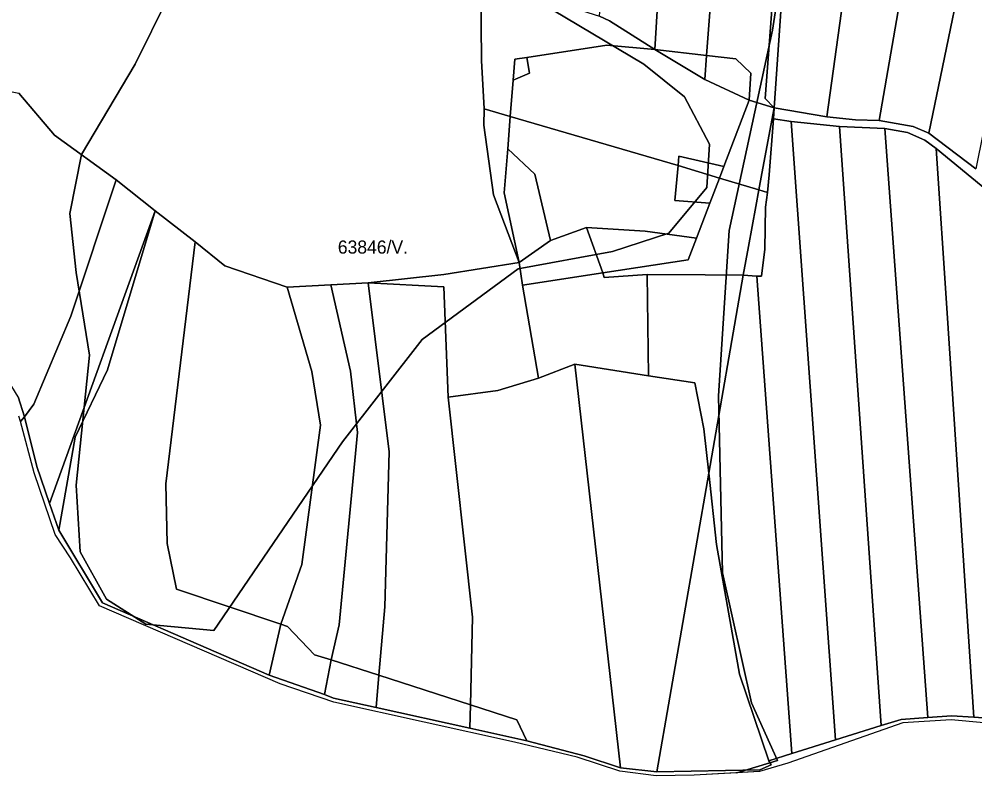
# Model space of a CAD drawing. Extents: x -521261 to -517465, y -1182764 to -1179456.
# Drawn here: x -519763.3 to -519398.8, y -1182348.9 to -1182060.3 of the extents above; entities that cross this region are included whole.
import ezdxf

# ---------------------------------------------------------------- set-up
doc = ezdxf.new("R2010")
doc.units = 0
for name, color, linetype in [('95560013', 7, 'Continuous'), ('95640013', 7, 'Continuous'), ('95660013', 7, 'Continuous')]:
    doc.layers.add(name, color=color, linetype=linetype)

msp = doc.modelspace()

# ---------------------------------------------------------------- linework, layer by layer
at = {"layer": '95560013'}
for points in [[(-519516.92, -1181853.55), (-519508.53, -1181867.8), (-519520.78, -1182071.93), (-519538.16, -1182060.97), (-519541.91, -1182059.26), (-519523.41, -1181832.63)], [(-519487.9, -1181902.3), (-519501.15, -1182074.26), (-519520.78, -1182071.93), (-519508.53, -1181867.8)], [(-519467.21, -1181936.45), (-519478.73, -1182090.66), (-519475.35, -1182094.14), (-519484.89, -1182091.25), (-519484.16, -1182080.96), (-519489.93, -1182075.44), (-519501.15, -1182074.26), (-519487.9, -1181902.3)], [(-519379, -1181923.14), (-519358.09, -1181917.7), (-519398.37, -1182117.43), (-519416.36, -1182103.79)], [(-519406.08, -1181930.21), (-519379, -1181923.14), (-519416.36, -1182103.79), (-519422.3, -1182101.28), (-519435.27, -1182098.99)], [(-519432.56, -1181934.33), (-519406.08, -1181930.21), (-519435.27, -1182098.99), (-519444.29, -1182098.72), (-519455.23, -1182097.62)], [(-519464.46, -1181937.6), (-519432.56, -1181934.33), (-519455.23, -1182097.62), (-519475.35, -1182094.14)], [(-519587.21, -1182048.68), (-519567.33, -1182051.07), (-519541.91, -1182059.26), (-519538.16, -1182060.97), (-519520.78, -1182071.93), (-519539.14, -1182070.29), (-519569.64, -1182074.9), (-519574.23, -1182075.58), (-519574.86, -1182083.63), (-519575.95, -1182097.41), (-519585.88, -1182094.5), (-519586.88, -1182076.07)], [(-519763.35, -1182088.59), (-519749.77, -1182104.53), (-519726.21, -1182121.6), (-519743.53, -1182173.62), (-519757.71, -1182207.2), (-519761.2, -1182211.94), (-519763.67, -1182204.39), (-519774.58, -1182186.72), (-519789.17, -1182168.41), (-519776.4, -1182108.82), (-519776, -1182086.02)], [(-519475.35, -1182094.14), (-519480.05, -1182119.2), (-519481.13, -1182125.46), (-519496.19, -1182120.92), (-519494.5, -1182116.48), (-519484.89, -1182091.25)], [(-519585.88, -1182094.5), (-519575.95, -1182097.41), (-519576.94, -1182109.82), (-519578.27, -1182126.51), (-519572.56, -1182153.16), (-519582.31, -1182127.3), (-519586.07, -1182100.76)], [(-519475.58, -1182098.3), (-519477.24, -1182119.69), (-519477.83, -1182126.45), (-519481.13, -1182125.46), (-519480.05, -1182119.2), (-519475.35, -1182094.14)], [(-519468.81, -1182099.37), (-519451.94, -1182335.19), (-519468.6, -1182340.44), (-519481.96, -1182158.34), (-519480.13, -1182158.37), (-519478.87, -1182148.03), (-519478.68, -1182132.07), (-519477.83, -1182126.45), (-519477.24, -1182119.69), (-519475.58, -1182098.3)], [(-519450.44, -1182101.26), (-519434.44, -1182329.73), (-519451.94, -1182335.19), (-519468.81, -1182099.37)], [(-519433.08, -1182101.99), (-519416.65, -1182326.64), (-519426.88, -1182327.36), (-519434.44, -1182329.73), (-519450.44, -1182101.26)], [(-519424.5, -1182103.59), (-519417.83, -1182106.43), (-519413.54, -1182109.63), (-519409.28, -1182172.45), (-519399.15, -1182326.59), (-519407.66, -1182325.98), (-519416.65, -1182326.64), (-519433.08, -1182101.99)], [(-519394.19, -1182125.51), (-519378.51, -1182327.95), (-519378.06, -1182331.92), (-519379.66, -1182331.75), (-519384.54, -1182331.48), (-519384.34, -1182329.69), (-519384.76, -1182327.55), (-519399.15, -1182326.59), (-519409.28, -1182172.45), (-519413.54, -1182109.63)], [(-519711.36, -1182133.5), (-519751.72, -1182245.06), (-519756.54, -1182230.97), (-519761.2, -1182211.94), (-519757.71, -1182207.2), (-519743.53, -1182173.62), (-519726.21, -1182121.6)], [(-519496.19, -1182120.92), (-519481.13, -1182125.46), (-519482.3, -1182131.8), (-519485.13, -1182147.09), (-519487.14, -1182158), (-519501.6, -1182157.81), (-519523.78, -1182157.71), (-519540.1, -1182158.81), (-519540.71, -1182157.1), (-519508.06, -1182152.07), (-519504.91, -1182143.82), (-519499.84, -1182130.5)], [(-519481.13, -1182125.46), (-519477.83, -1182126.45), (-519478.68, -1182132.07), (-519478.87, -1182148.03), (-519480.13, -1182158.37), (-519481.96, -1182158.34), (-519487.14, -1182158), (-519485.13, -1182147.09), (-519482.3, -1182131.8)], [(-519696.09, -1182145.3), (-519684.77, -1182154.35), (-519661.04, -1182162.55), (-519651.69, -1182194.65), (-519648.28, -1182215.2), (-519655.4, -1182268.32), (-519663.51, -1182291.01), (-519703.24, -1182277.77), (-519706.82, -1182260.27), (-519707.29, -1182237.56)], [(-519572.56, -1182153.16), (-519571.25, -1182161.79), (-519565.14, -1182197.26), (-519580.66, -1182201.92), (-519599.71, -1182204.55), (-519601.3, -1182162.43), (-519630.15, -1182160.89), (-519601.35, -1182157.71)], [(-519540.1, -1182158.81), (-519523.78, -1182157.71), (-519523.29, -1182196.42), (-519551.35, -1182191.91), (-519565.14, -1182197.26), (-519571.25, -1182161.79), (-519540.71, -1182157.1)], [(-519523.78, -1182157.71), (-519501.6, -1182157.81), (-519487.14, -1182158), (-519500.27, -1182233.5), (-519502.08, -1182216.63), (-519505.57, -1182199.06), (-519523.29, -1182196.42)], [(-519481.96, -1182158.34), (-519468.6, -1182340.44), (-519477.29, -1182343.21), (-519488.55, -1182310.14), (-519497.35, -1182260.74), (-519500.27, -1182233.5), (-519487.14, -1182158)], [(-519644.35, -1182161.65), (-519636.84, -1182194.61), (-519634.17, -1182218), (-519641.18, -1182291.32), (-519644.33, -1182304.67), (-519650.66, -1182302.72), (-519660.94, -1182291.93), (-519663.51, -1182291.01), (-519655.4, -1182268.32), (-519648.28, -1182215.2), (-519651.69, -1182194.65), (-519661.04, -1182162.55)], [(-519630.15, -1182160.89), (-519622.19, -1182225.4), (-519623.76, -1182284.43), (-519626.06, -1182310.56), (-519644.33, -1182304.67), (-519641.18, -1182291.32), (-519634.17, -1182218), (-519636.84, -1182194.61), (-519644.35, -1182161.65)], [(-519630.15, -1182160.89), (-519601.3, -1182162.43), (-519599.71, -1182204.55), (-519590.36, -1182288.36), (-519591.16, -1182321.81), (-519626.06, -1182310.56), (-519623.76, -1182284.43), (-519622.19, -1182225.4)], [(-519551.35, -1182191.91), (-519533.95, -1182345.85), (-519547.75, -1182341.3), (-519569.7, -1182335.58), (-519573.45, -1182327.52), (-519591.16, -1182321.81), (-519590.36, -1182288.36), (-519599.71, -1182204.55), (-519580.66, -1182201.92), (-519565.14, -1182197.26)], [(-519523.29, -1182196.42), (-519505.57, -1182199.06), (-519502.08, -1182216.63), (-519500.27, -1182233.5), (-519520.08, -1182347.41), (-519533.95, -1182345.85), (-519551.35, -1182191.91)], [(-519500.27, -1182233.5), (-519497.35, -1182260.74), (-519488.55, -1182310.14), (-519477.29, -1182343.21), (-519476.43, -1182344.74), (-519480.75, -1182346.56), (-519520.08, -1182347.41)]]:
    msp.add_lwpolyline(points, close=True, dxfattribs=at)
for points in [[(-519587.21, -1182048.68), (-519586.88, -1182076.07), (-519585.88, -1182094.5), (-519586.07, -1182100.76), (-519582.31, -1182127.3), (-519572.56, -1182153.16), (-519601.35, -1182157.71), (-519630.15, -1182160.89), (-519644.35, -1182161.65), (-519661.04, -1182162.55), (-519684.77, -1182154.35), (-519696.09, -1182145.3), (-519711.36, -1182133.5), (-519726.21, -1182121.6), (-519749.77, -1182104.53), (-519763.35, -1182088.59)], [(-519394.19, -1182125.51), (-519413.54, -1182109.63), (-519417.83, -1182106.43), (-519424.5, -1182103.59), (-519433.08, -1182101.99), (-519450.44, -1182101.26), (-519468.81, -1182099.37), (-519475.58, -1182098.3), (-519475.35, -1182094.14), (-519455.23, -1182097.62), (-519444.29, -1182098.72), (-519435.27, -1182098.99), (-519422.3, -1182101.28), (-519416.36, -1182103.79), (-519398.37, -1182117.43)], [(-519763.67, -1182204.39), (-519761.2, -1182211.94), (-519762.82, -1182213.81), (-519763.37, -1182211.75)]]:
    msp.add_lwpolyline(points, dxfattribs=at)
at = {"layer": '95640013'}
for points in [[(-519531.67, -1181805.67), (-519527.59, -1181810.9), (-519514.79, -1181851.2), (-519465.56, -1181934.8), (-519464.46, -1181937.6), (-519475.35, -1182094.14), (-519478.73, -1182090.66), (-519467.21, -1181936.45), (-519487.9, -1181902.3), (-519508.53, -1181867.8), (-519516.92, -1181853.55), (-519523.41, -1181832.63), (-519529.03, -1181814.46), (-519530.74, -1181812.82)], [(-519539.14, -1182070.29), (-519520.78, -1182071.93), (-519501.8, -1182083.31), (-519484.89, -1182091.25), (-519494.5, -1182116.48), (-519511.65, -1182112.55), (-519511.94, -1182116.17), (-519575.95, -1182097.41), (-519574.86, -1182083.63), (-519568.69, -1182080.98), (-519569.64, -1182074.9)], [(-519520.78, -1182071.93), (-519501.15, -1182074.26), (-519501.8, -1182083.31)], [(-519501.15, -1182074.26), (-519489.93, -1182075.44), (-519484.16, -1182080.96), (-519484.89, -1182091.25), (-519501.8, -1182083.31)], [(-519574.23, -1182075.58), (-519569.64, -1182074.9), (-519568.69, -1182080.98), (-519574.86, -1182083.63)], [(-519576.94, -1182109.82), (-519575.95, -1182097.41), (-519511.94, -1182116.17), (-519513.2, -1182129.51), (-519499.84, -1182130.5), (-519504.91, -1182143.82), (-519524.51, -1182141.21), (-519546.92, -1182139.79), (-519560.67, -1182144.76), (-519566.54, -1182119.49)], [(-519576.94, -1182109.82), (-519566.54, -1182119.49), (-519560.67, -1182144.76), (-519572.56, -1182153.16), (-519578.27, -1182126.51)], [(-519511.94, -1182116.17), (-519511.65, -1182112.55), (-519494.5, -1182116.48), (-519496.19, -1182120.92)], [(-519511.94, -1182116.17), (-519496.19, -1182120.92), (-519499.84, -1182130.5), (-519513.2, -1182129.51)], [(-519711.36, -1182133.5), (-519729.53, -1182194.03), (-519741.92, -1182219.81), (-519748.2, -1182255.2), (-519751.72, -1182245.06)], [(-519696.09, -1182145.3), (-519707.29, -1182237.56), (-519706.82, -1182260.27), (-519703.24, -1182277.77), (-519663.51, -1182291.01), (-519667.93, -1182310.48), (-519731.54, -1182282.88), (-519748.2, -1182255.2), (-519741.92, -1182219.81), (-519729.53, -1182194.03), (-519711.36, -1182133.5)], [(-519546.92, -1182139.79), (-519540.71, -1182157.1), (-519571.25, -1182161.79), (-519572.56, -1182153.16), (-519560.67, -1182144.76)], [(-519524.51, -1182141.21), (-519504.91, -1182143.82), (-519508.06, -1182152.07), (-519540.71, -1182157.1), (-519546.92, -1182139.79)], [(-519660.94, -1182291.93), (-519650.66, -1182302.72), (-519644.33, -1182304.67), (-519646.86, -1182317.92), (-519667.93, -1182310.48), (-519663.51, -1182291.01)], [(-519626.06, -1182310.56), (-519627.14, -1182322.79), (-519643.33, -1182319.25), (-519646.86, -1182317.92), (-519644.33, -1182304.67)], [(-519591.16, -1182321.81), (-519591.37, -1182330.69), (-519627.14, -1182322.79), (-519626.06, -1182310.56)], [(-519573.45, -1182327.52), (-519569.7, -1182335.58), (-519591.37, -1182330.69), (-519591.16, -1182321.81)]]:
    msp.add_lwpolyline(points, close=True, dxfattribs=at)
msp.add_lwpolyline([(-519384.34, -1182329.69), (-519407.79, -1182327.6), (-519426.27, -1182328.75), (-519470.15, -1182344.05), (-519480.86, -1182347.27), (-519505.85, -1182348.7), (-519520.37, -1182348.92), (-519534.18, -1182347.06), (-519550.42, -1182341.81), (-519574.39, -1182336.12), (-519643.28, -1182320.8), (-519663.67, -1182313.8), (-519732.68, -1182284.01), (-519743.73, -1182265.8), (-519749.55, -1182256.9), (-519757.57, -1182233.31), (-519762.82, -1182213.81), (-519761.2, -1182211.94), (-519756.54, -1182230.97), (-519751.72, -1182245.06), (-519748.2, -1182255.2), (-519731.54, -1182282.88), (-519667.93, -1182310.48), (-519646.86, -1182317.92), (-519643.33, -1182319.25), (-519627.14, -1182322.79), (-519591.37, -1182330.69), (-519569.7, -1182335.58), (-519547.75, -1182341.3), (-519533.95, -1182345.85), (-519520.08, -1182347.41), (-519480.75, -1182346.56), (-519476.43, -1182344.74), (-519477.29, -1182343.21), (-519468.6, -1182340.44), (-519451.94, -1182335.19), (-519434.44, -1182329.73), (-519426.88, -1182327.36), (-519416.65, -1182326.64), (-519407.66, -1182325.98), (-519399.15, -1182326.59), (-519384.76, -1182327.55)], dxfattribs=at)
at = {"layer": '95660013'}
for points in [[(-519466, -1182000), (-519476, -1182064.5), (-519492.5, -1182141), (-519496.5, -1182204), (-519495, -1182271.5), (-519484, -1182321), (-519474, -1182343), (-519489.54, -1182347.77), (-519505.85, -1182348.7), (-519520.37, -1182348.92), (-519534.18, -1182347.06), (-519550.42, -1182341.81), (-519574.39, -1182336.12), (-519643.28, -1182320.8), (-519663.67, -1182313.8), (-519732.68, -1182284.01), (-519743.73, -1182265.8), (-519749.55, -1182256.9), (-519757.57, -1182233.31), (-519762.82, -1182213.81), (-519763.37, -1182211.75)], [(-519327, -1182051), (-519350, -1182136.5), (-519373, -1182249), (-519374, -1182294), (-519368, -1182328), (-519367.34, -1182332.84), (-519372.3, -1182332.49), (-519378.06, -1182331.92), (-519379.66, -1182331.75), (-519384.54, -1182331.48), (-519384.34, -1182329.69), (-519407.79, -1182327.6), (-519426.27, -1182328.75), (-519470.15, -1182344.05), (-519480.86, -1182347.27), (-519489.54, -1182347.77), (-519474, -1182343), (-519484, -1182321), (-519495, -1182271.5), (-519496.5, -1182204), (-519492.5, -1182141), (-519476, -1182064.5), (-519466, -1182000)], [(-519564.5, -1182054), (-519525, -1182077.5), (-519509.5, -1182090), (-519500, -1182108), (-519501, -1182124.5), (-519515.5, -1182142), (-519537, -1182149), (-519573, -1182155.5), (-519609.5, -1182182.5), (-519640, -1182221.5), (-519689, -1182293.5), (-519715, -1182291), (-519730, -1182281.5), (-519740, -1182263.5), (-519741.5, -1182238), (-519736.5, -1182188.5), (-519741.5, -1182157), (-519744, -1182134.5), (-519739.5, -1182112), (-519719, -1182077.5), (-519706.5, -1182052)], [(-519706.5, -1182052), (-519719, -1182077.5), (-519739.5, -1182112), (-519744, -1182134.5), (-519741.5, -1182157), (-519736.5, -1182188.5), (-519741.5, -1182238), (-519740, -1182263.5), (-519730, -1182281.5), (-519715, -1182291), (-519689, -1182293.5), (-519640, -1182221.5), (-519609.5, -1182182.5), (-519573, -1182155.5), (-519537, -1182149), (-519515.5, -1182142), (-519501, -1182124.5), (-519500, -1182108), (-519509.5, -1182090), (-519525, -1182077.5), (-519564.5, -1182054)]]:
    msp.add_lwpolyline(points, dxfattribs=at)

# ---------------------------------------------------------------- texts
msp.add_text('63846/V.', height=5, rotation=0, dxfattribs=at).set_placement((-519641.73, -1182149.75))

doc.saveas('drawing.dxf')
